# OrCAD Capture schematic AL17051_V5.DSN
size Custom; title: AL17051, ULTRA LOW STANDBY POWER HV BUCK CONVERTER; rev: 1.0; note: DS44934_REV.2-2
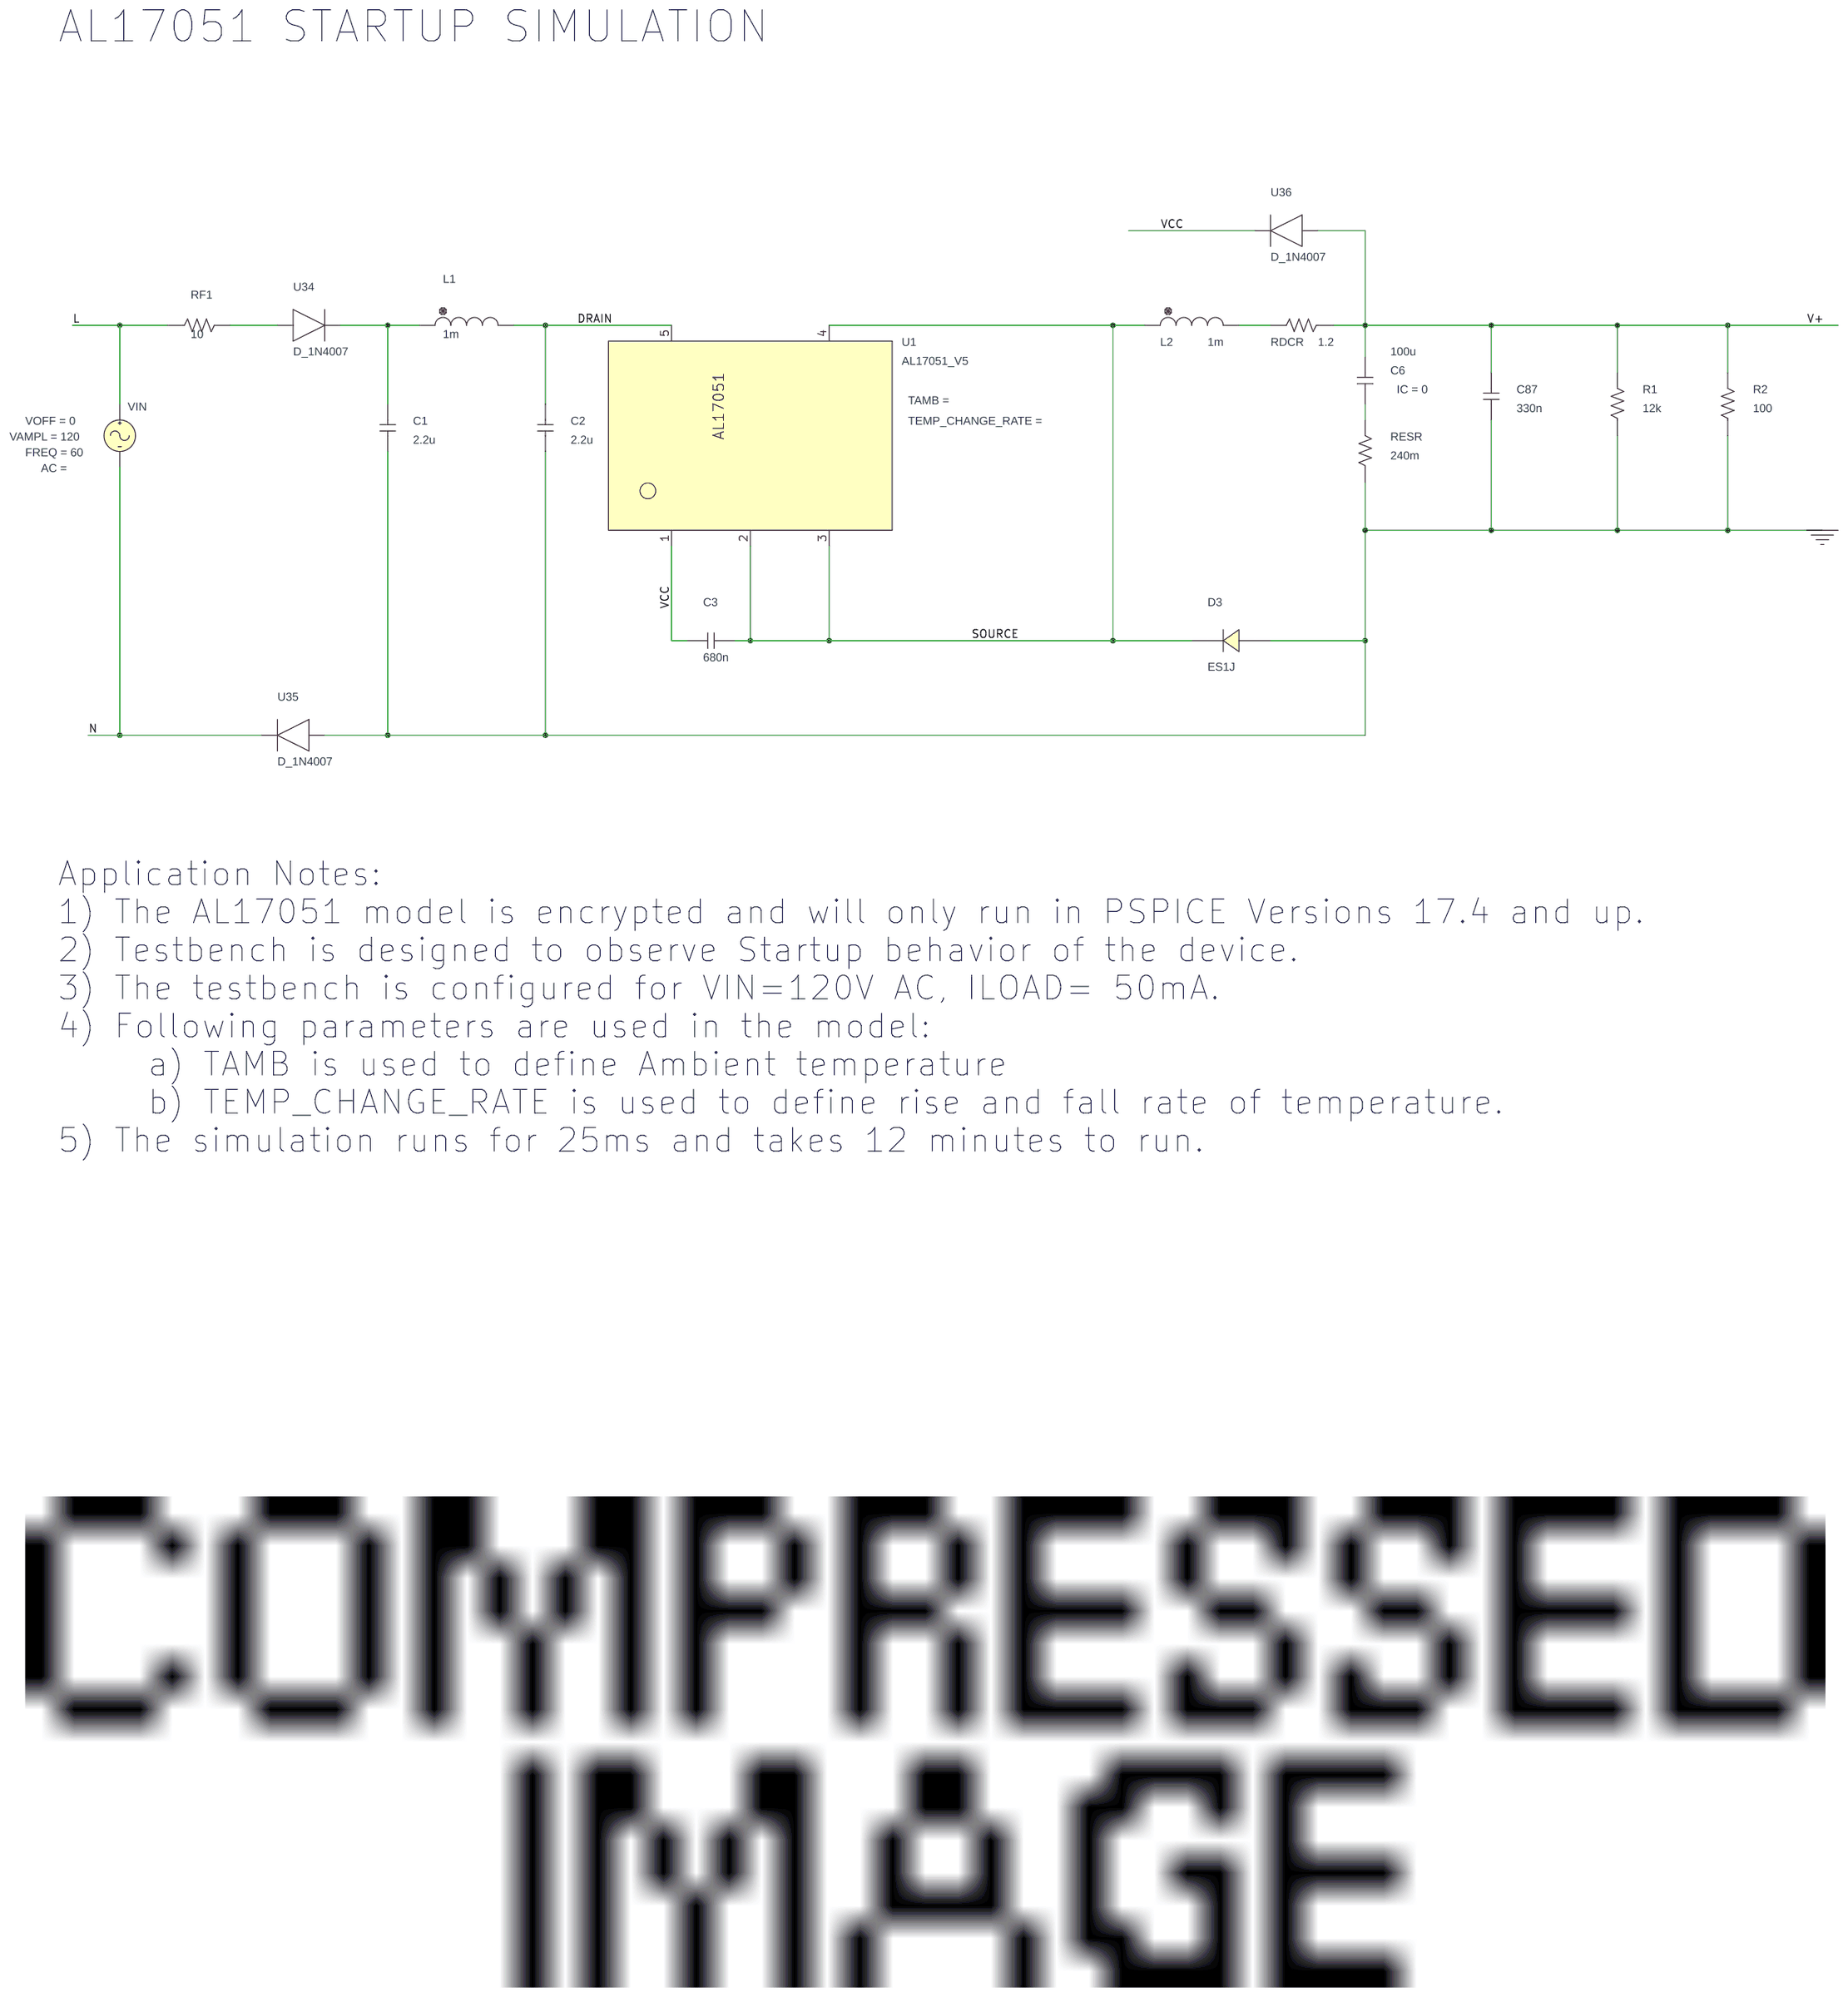
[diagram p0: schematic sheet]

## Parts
C1  2.2u  [RAD/CK05]
C2  2.2u  [RAD/CK05]
C3  680n  [RAD/CK05]
C6  100u  [RAD/CK05]
C87  330n  [RAD/CK05]
D3  ES1J
L1  1m  [DISC/.350x.175/LS.200x.100/.034]
L2  1m  [DISC/.350x.175/LS.200x.100/.034]
R1  12k  [AX/RC05]
R2  100  [AX/RC05]
RDCR  1.2  [AX/RC05]
RESR  240m  [AX/RC05]
RF1  10  [AX/RC05]
U1  AL17051_V5
U34  D_1N4007
U35  D_1N4007
U36  D_1N4007
VIN  VSIN

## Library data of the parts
C1 C2 C87 = C
C3 C6 = C: IC: 0
D3 = ES1J
L1 L2 = L
R1 R2 RDCR RESR RF1 = R
U1 = AL17051_V5
U34-U36 = D_1N4007
VIN = VSIN: FREQ: 60; VAMPL: 120; VOFF: 0

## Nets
VCC: C3.1 U1.1(VCC) U36.2
0: C1.1 C2.1 C87.1 D3.1 R1.1 R2.1 RESR.1 U35.1
DRAIN: C2.2 L1.2 U1.5(DRAIN)
L: RF1.1 VIN.1(+)
N: U35.2 VIN.2(-)
SOURCE: C3.2 D3.2 L2.1 U1.2(SOURCE_1) U1.3(SOURCE_2) U1.4(SOURCE_3)
V+: C6.1 C87.2 R1.2 R2.2 RDCR.1 U36.1
N16436885: RF1.2 U34.1
N16436891: C1.2 L1.1 U34.2
N16436933: L2.2 RDCR.2
N16437077: C6.2 RESR.2

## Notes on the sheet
- AL17051 STARTUP SIMULATION
- Application Notes:
  1) The AL17051 model is encrypted and will only run in PSPICE Versions 17.4 and up.
  2) Testbench is designed to observe Startup behavior of the device.
  3) The testbench is configured for VIN=120V AC, ILOAD= 50mA.
  4) Following parameters are used in the model:
       a) TAMB is used to define Ambient temperature
       b) TEMP_CHANGE_RATE is used to define rise and fall rate of temperature.
  5) The simulation runs for 25ms and takes 12 minutes to run.
